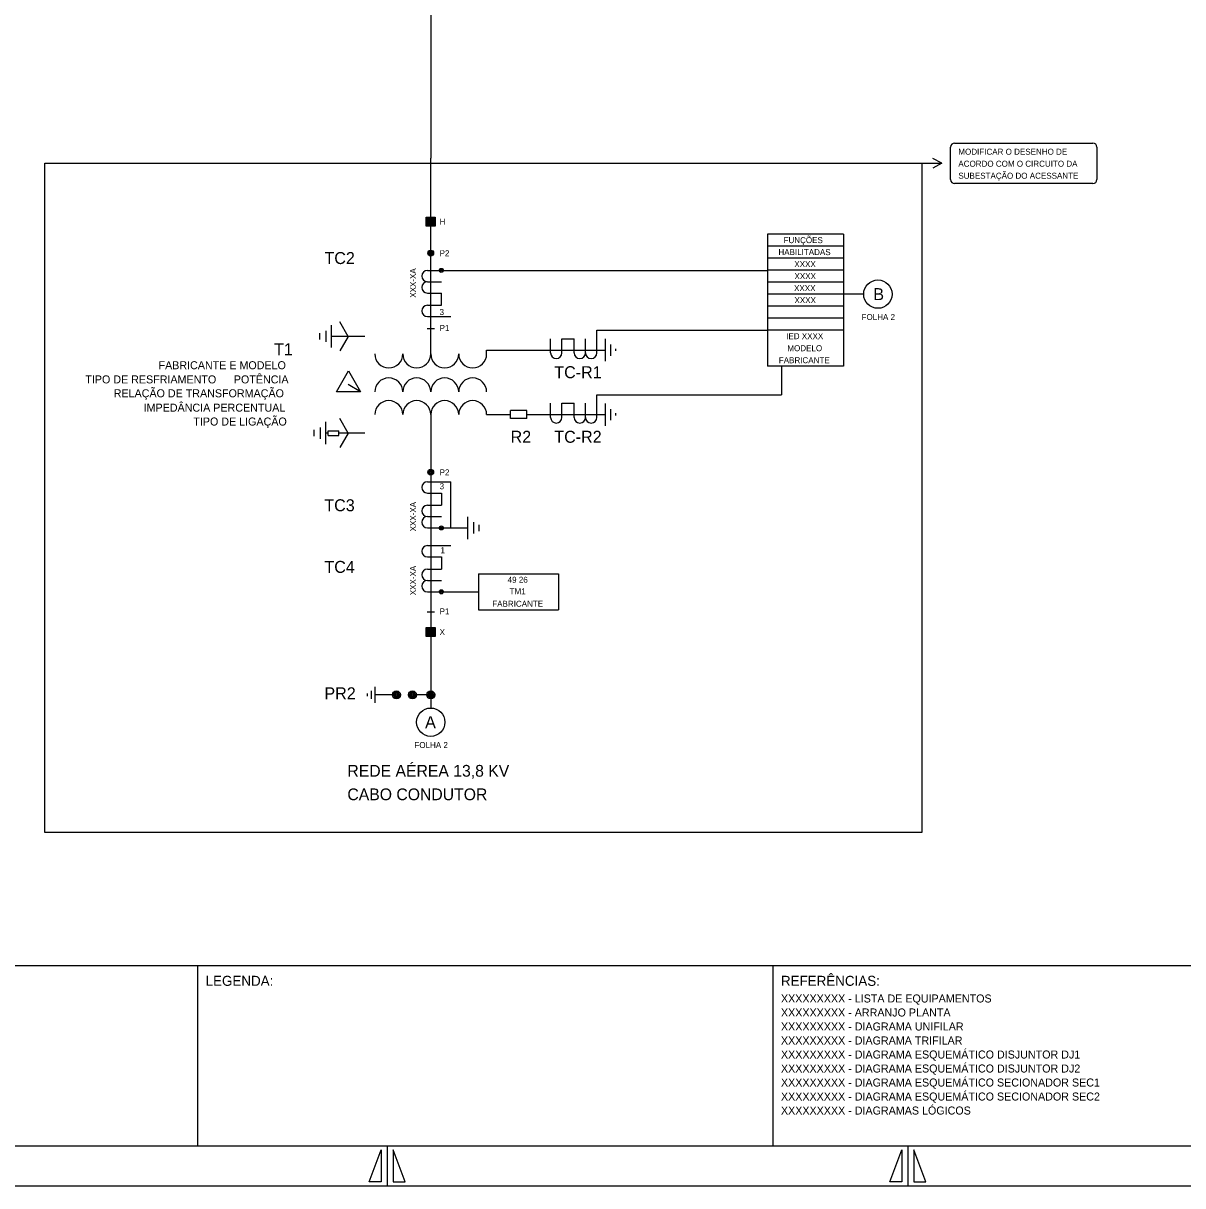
# Model space of a CAD drawing. Extents: x 563 to 1404, y 358 to 952.
# Drawn here: x 812.7 to 1102.2, y 358 to 648.4 of the extents above; entities that cross this region are included whole.
import ezdxf

# ---------------------------------------------------------------- set-up
doc = ezdxf.new("R2010")
doc.units = 0
doc.layers.add('New Level (0)', color=7, linetype='Continuous')

msp = doc.modelspace()

# ---------------------------------------------------------------- linework, layer by layer
for p, q in [((914.46, 705.43), (914.46, 614.76)), ((914.46, 565.81), (914.46, 614.76)), ((913.34, 597.79), (915.49, 599.94)), ((913.34, 597.96), (915.32, 599.94)), ((913.34, 598.14), (915.14, 599.94)), ((913.34, 598.32), (914.96, 599.94)), ((913.34, 598.49), (914.79, 599.94)), ((913.34, 598.67), (914.61, 599.94)), ((913.34, 598.85), (914.43, 599.94)), ((913.34, 599.02), (914.26, 599.94)), ((913.34, 599.2), (914.08, 599.94)), ((913.34, 599.38), (913.9, 599.94)), ((913.34, 599.55), (913.73, 599.94)), ((913.34, 599.73), (913.55, 599.94)), ((913.34, 599.91), (913.37, 599.94)), ((913.46, 597.73), (915.55, 599.82)), ((913.64, 597.73), (915.55, 599.64)), ((913.81, 597.73), (915.55, 599.47)), ((913.99, 597.73), (915.55, 599.29)), ((914.17, 597.73), (915.55, 599.11)), ((914.34, 597.73), (915.55, 598.94)), ((914.52, 597.73), (915.55, 598.76)), ((914.7, 597.73), (915.55, 598.58)), ((914.87, 597.73), (915.55, 598.41)), ((915.05, 597.73), (915.55, 598.23)), ((915.23, 597.73), (915.55, 598.05)), ((915.4, 597.73), (915.55, 597.88)), ((998.51, 595.74), (998.51, 562.74)), ((1017.49, 595.74), (998.51, 595.74)), ((1017.49, 595.74), (1017.49, 562.74)), ((1017.49, 592.74), (998.51, 592.74)), ((1017.49, 589.74), (998.51, 589.74)), ((913.64, 586.67), (998.51, 586.67)), ((1017.49, 586.74), (998.51, 586.74)), ((913.64, 583.84), (917.18, 583.84)), ((913.64, 581.01), (917.18, 581.01)), ((917.18, 577.96), (917.18, 581.01)), ((1017.49, 583.74), (998.51, 583.74)), ((1022.57, 580.74), (998.51, 580.74)), ((913.64, 577.96), (917.18, 577.96)), ((1017.49, 577.74), (998.51, 577.74)), ((1017.49, 577.74), (998.51, 577.74)), ((889.65, 567.4), (889.65, 572.99)), ((893.84, 570.19), (891.75, 573.82)), ((913.64, 575.13), (919.51, 575.13)), ((1017.49, 574.74), (998.51, 574.74)), ((886.77, 569.41), (886.77, 570.97)), ((888.25, 571.59), (888.25, 568.8)), ((898.03, 570.19), (889.65, 570.19)), ((893.84, 570.19), (891.75, 566.56)), ((944.39, 566.07), (944.39, 569.61)), ((947.22, 569.61), (950.27, 569.61)), ((947.22, 566.07), (947.22, 569.61)), ((950.27, 566.07), (950.27, 569.61)), ((953.1, 566.07), (953.1, 569.61)), ((955.93, 566.07), (955.93, 571.74)), ((955.93, 571.74), (998.51, 571.74)), ((958.05, 569.56), (958.05, 563.98)), ((1017.49, 571.74), (998.51, 571.74)), ((928.42, 566.77), (958.05, 566.77)), ((928.42, 565.81), (928.42, 566.77)), ((959.44, 565.37), (959.44, 568.17)), ((960.61, 567.11), (960.61, 566.57)), ((890.88, 556.32), (893.91, 561.56)), ((893.91, 561.56), (896.93, 556.32)), ((1017.49, 562.74), (998.51, 562.74)), ((1002.01, 562.74), (1002.01, 555.6)), ((896.93, 556.32), (893.84, 558.19)), ((896.93, 556.32), (890.88, 556.32)), ((955.93, 549.94), (955.93, 555.6)), ((955.93, 555.6), (1002.01, 555.6)), ((944.39, 549.94), (944.39, 553.48)), ((947.22, 553.48), (950.27, 553.48)), ((947.22, 549.94), (947.22, 553.48)), ((950.27, 549.94), (950.27, 553.48)), ((953.1, 549.94), (953.1, 553.48)), ((958.05, 553.43), (958.05, 547.84)), ((959.44, 549.24), (959.44, 552.03)), ((893.84, 546.02), (891.75, 549.65)), ((928.42, 550.64), (934.39, 550.64)), ((934.39, 549.63), (934.39, 551.65)), ((938.42, 551.65), (934.39, 551.65)), ((938.42, 549.63), (934.39, 549.63)), ((938.42, 549.63), (938.42, 551.65)), ((938.42, 550.64), (958.05, 550.64)), ((960.61, 550.98), (960.61, 550.44)), ((885.38, 545.24), (885.38, 546.8)), ((886.86, 547.42), (886.86, 544.62)), ((888.25, 543.23), (888.25, 548.81)), ((888.83, 546.02), (888.25, 546.02)), ((898.03, 546.02), (891.52, 546.02)), ((893.84, 546.02), (891.75, 542.39)), ((913.64, 533.87), (919.51, 533.87)), ((913.64, 531.04), (917.18, 531.04)), ((917.18, 531.04), (917.18, 527.99)), ((913.64, 527.99), (917.18, 527.99)), ((913.64, 525.16), (917.18, 525.16)), ((923.7, 519.54), (923.7, 525.12)), ((925.1, 523.73), (925.1, 520.93)), ((926.58, 521.55), (926.58, 523.11)), ((913.64, 522.33), (917.18, 522.33)), ((917.18, 522.33), (923.7, 522.33)), ((913.64, 517.91), (919.51, 517.91)), ((913.64, 515.08), (917.18, 515.08)), ((917.18, 515.08), (917.18, 512.03)), ((913.64, 512.03), (917.18, 512.03)), ((913.64, 509.2), (917.18, 509.2)), ((926.38, 510.87), (926.38, 501.87)), ((926.38, 510.87), (946.37, 510.87)), ((946.37, 510.87), (946.37, 501.87)), ((913.64, 506.37), (926.38, 506.37)), ((913.64, 506.37), (917.18, 506.37)), ((926.38, 501.87), (946.37, 501.87)), ((913.34, 495.27), (915.49, 497.42)), ((913.34, 495.44), (915.32, 497.42)), ((913.34, 495.62), (915.14, 497.42)), ((913.34, 495.8), (914.96, 497.42)), ((913.34, 495.97), (914.79, 497.42)), ((913.34, 496.15), (914.61, 497.42)), ((913.34, 496.33), (914.43, 497.42)), ((913.34, 496.5), (914.26, 497.42)), ((913.34, 496.68), (914.08, 497.42)), ((913.34, 496.86), (913.9, 497.42)), ((913.34, 497.04), (913.73, 497.42)), ((913.34, 497.21), (913.55, 497.42)), ((913.34, 497.39), (913.37, 497.42)), ((913.46, 495.21), (915.55, 497.3)), ((913.64, 495.21), (915.55, 497.12)), ((913.81, 495.21), (915.55, 496.95)), ((913.99, 495.21), (915.55, 496.77)), ((914.17, 495.21), (915.55, 496.59)), ((914.34, 495.21), (915.55, 496.42)), ((914.52, 495.21), (915.55, 496.24)), ((914.7, 495.21), (915.55, 496.06)), ((914.87, 495.21), (915.55, 495.89)), ((915.05, 495.21), (915.55, 495.71)), ((915.23, 495.21), (915.55, 495.53)), ((915.4, 495.21), (915.55, 495.36)), ((900.57, 478.62), (900.57, 482.62)), ((898.57, 480.92), (898.57, 480.32)), ((898.57, 480.62), (898.57, 480.62)), ((899.57, 481.62), (899.57, 479.62)), ((901.89, 480.62), (900.57, 480.62)), ((905.89, 480.62), (901.89, 480.62)), ((914.47, 480.62), (909.89, 480.62))]:
    msp.add_line(p, q)
for points in [[(913.34, 599.94), (915.55, 599.94), (915.55, 597.73), (913.34, 597.73)], [(913.34, 497.42), (915.55, 497.42), (915.55, 495.21), (913.34, 495.21)]]:
    msp.add_lwpolyline(points, close=True)
for centre, radius in [((914.45, 591.01), 0.729), ((914.46, 591), 0.511), ((914.46, 591), 0.288), ((917.09, 586.67), 0.511), ((917.09, 586.67), 0.288), ((914.45, 536.24), 0.729), ((914.46, 536.24), 0.511), ((914.46, 536.24), 0.288), ((917.1, 522.33), 0.511), ((917.1, 522.33), 0.288), ((917.09, 506.37), 0.511), ((917.09, 506.37), 0.288), ((905.89, 480.62), 1), ((905.89, 480.62), 0.75), ((905.89, 480.62), 0.5), ((905.89, 480.62), 0.25), ((909.89, 480.62), 1), ((909.89, 480.62), 0.75), ((909.89, 480.62), 0.5), ((909.89, 480.62), 0.25), ((914.47, 480.62), 1), ((914.47, 480.62), 0.75), ((914.47, 480.62), 0.5), ((914.47, 480.62), 0.25)]:
    msp.add_circle(centre, radius)
for centre, radius, start, end in [((913.64, 585.26), 1.42, 90, 270), ((913.64, 582.43), 1.42, 90, 270), ((913.64, 576.54), 1.42, 90, 270), ((903.98, 565.81), 3.49, 180, 0), ((910.96, 565.81), 3.49, 180, 0), ((917.95, 565.81), 3.49, 180, 0), ((924.93, 565.81), 3.49, 180, 0), ((945.8, 566.07), 1.42, 180, 0), ((951.68, 566.07), 1.42, 180, 0), ((954.51, 566.07), 1.42, 180, 0), ((903.98, 556.32), 3.49, 0, 180), ((910.96, 556.32), 3.49, 0, 180), ((917.95, 556.32), 3.49, 0, 180), ((924.93, 556.32), 3.49, 0, 180), ((903.98, 550.64), 3.49, 0, 180), ((910.96, 550.64), 3.49, 0, 180), ((917.95, 550.64), 3.49, 0, 180), ((924.93, 550.64), 3.49, 0, 180), ((945.8, 549.94), 1.42, 180, 0), ((951.68, 549.94), 1.42, 180, 0), ((954.51, 549.94), 1.42, 180, 0), ((913.64, 532.46), 1.42, 90, 270), ((913.64, 526.58), 1.42, 90, 270), ((913.64, 523.75), 1.42, 90, 270), ((913.64, 516.5), 1.42, 90, 270), ((913.64, 510.62), 1.42, 90, 270), ((913.64, 507.79), 1.42, 90, 270)]:
    msp.add_arc(centre, radius, start, end)
at = {"layer": 'New Level (0)'}
for p, q in [((1044.27, 609.37), (1044.27, 617.49)), ((1045.27, 618.49), (1052.62, 618.49)), ((1052.62, 618.49), (1079.81, 618.49)), ((1080.81, 617.49), (1080.81, 609.37)), ((1037.08, 613.43), (1042.11, 613.43)), ((1042.11, 613.43), (1039.81, 614.64)), ((1042.11, 613.43), (1039.81, 612.22)), ((1079.81, 608.37), (1045.27, 608.37)), ((913.56, 572.17), (915.36, 572.17)), ((914.46, 550.64), (914.46, 477.34)), ((888.83, 546.02), (888.83, 546.63)), ((888.83, 546.63), (891.52, 546.63)), ((891.52, 545.41), (891.52, 546.63)), ((888.83, 545.41), (888.83, 546.02)), ((888.83, 545.41), (891.52, 545.41)), ((919.51, 522.33), (919.51, 533.87)), ((913.56, 501.35), (915.36, 501.35)), ((572.58, 412.96), (1393.58, 412.96)), ((856.24, 412.96), (856.24, 367.96)), ((999.91, 412.96), (999.91, 367.96)), ((572.58, 367.96), (1393.58, 367.96)), ((572.58, 367.96), (1393.58, 367.96)), ((899.08, 358.96), (902.08, 366.96)), ((902.08, 366.96), (902.08, 358.96)), ((903.58, 367.96), (903.58, 357.96)), ((905.08, 366.96), (905.08, 358.96)), ((908.08, 358.96), (905.08, 366.96)), ((1029.08, 358.96), (1032.08, 366.96)), ((1032.08, 366.96), (1032.08, 358.96)), ((1033.58, 367.96), (1033.58, 357.96)), ((1035.08, 366.96), (1035.08, 358.96)), ((1038.08, 358.96), (1035.08, 366.96)), ((562.58, 357.96), (1403.58, 357.96)), ((562.58, 357.96), (1403.58, 357.96)), ((902.08, 358.96), (899.08, 358.96)), ((905.08, 358.96), (908.08, 358.96)), ((1032.08, 358.96), (1029.08, 358.96)), ((1035.08, 358.96), (1038.08, 358.96))]:
    msp.add_line(p, q, dxfattribs=at)
msp.add_lwpolyline([(818.09, 613.43), (1037.08, 613.43), (1037.08, 446.19), (818.09, 446.19)], close=True, dxfattribs=at)
for centre in [(1026.11, 580.74), (914.46, 473.79)]:
    msp.add_circle(centre, 3.54, dxfattribs=at)
for centre, start, end in [((1045.27, 617.49), 90, 180), ((1079.81, 617.49), 0, 90), ((1045.27, 609.37), 180, 270), ((1079.81, 609.37), 270, 0)]:
    msp.add_arc(centre, 1, start, end, dxfattribs=at)

# ---------------------------------------------------------------- texts
for s, height, p in [('MODIFICAR O DESENHO DE ', 1.5, (1046.21, 615.58)), ('ACORDO COM O CIRCUITO DA ', 1.5, (1046.21, 612.58)), ('SUBESTAÇÃO DO ACESSANTE', 1.5, (1046.21, 609.58)), ('H', 1.5, (916.67, 598.09)), ('FUNÇÕES ', 1.5, (1002.57, 593.49)), ('TC2', 3, (887.92, 588.26)), ('P2', 1.5, (916.67, 590.23)), ('HABILITADAS', 1.5, (1001.28, 590.49)), ('XXXX', 1.5, (1005.26, 587.49)), ('XXXX', 1.5, (1005.29, 584.49)), ('XXXX', 1.5, (1005.19, 581.49)), ('B', 3, (1024.98, 579.24)), ('XXXX', 1.5, (1005.29, 578.49)), ('3', 1.5, (916.66, 575.53)), ('FOLHA 2', 1.5, (1022.04, 574.28)), ('P1', 1.5, (916.67, 571.55)), ('IED XXXX', 1.5, (1003.22, 569.49)), ('T1', 3, (875.33, 565.45)), ('MODELO', 1.5, (1003.51, 566.49)), ('FABRICANTE E MODELO', 2, (846.48, 561.98)), ('FABRICANTE', 1.5, (1001.38, 563.49)), ('POTÊNCIA', 2, (865.28, 558.44)), ('TC-R1', 3, (945.32, 559.74)), ('TIPO DE RESFRIAMENTO ', 2, (828.2, 558.44)), ('RELAÇÃO DE TRANSFORMAÇÃO', 2, (835.29, 554.97)), ('IMPEDÂNCIA PERCENTUAL', 2, (842.76, 551.38)), ('TIPO DE LIGAÇÃO', 2, (855.17, 547.91)), ('R2', 3, (934.4, 543.6)), ('TC-R2', 3, (945.32, 543.6)), ('P2', 1.5, (916.67, 535.46)), ('3', 1.5, (916.67, 531.99)), ('TC3', 3, (887.89, 526.49)), ('1', 1.5, (916.88, 516.02)), ('TC4', 3, (887.91, 511.09)), ('49 26', 1.5, (933.66, 508.62)), ('TM1', 1.5, (934.14, 505.73)), ('FABRICANTE', 1.5, (929.82, 502.62)), ('P1', 1.5, (916.67, 500.72)), ('X', 1.5, (916.67, 495.57)), ('PR2', 3, (887.91, 479.5)), ('A', 3, (913.05, 472.29)), ('FOLHA 2', 1.5, (910.38, 467.33)), ('REDE AÉREA 13,8 KV', 2.94, (893.64, 460.17)), ('CABO CONDUTOR ', 2.94, (893.64, 454.29))]:
    msp.add_text(s, height=height).set_placement(p)
for p in [(910.77, 579.85), (910.77, 521.47), (910.77, 505.51)]:
    msp.add_text('XXX-XA', height=1.5, rotation=90).set_placement(p)
for s, height, p in [('LEGENDA:', 2.5, (858.24, 407.91)), ('REFERÊNCIAS:', 2.5, (1001.91, 407.91)), ('XXXXXXXXX - LISTA DE EQUIPAMENTOS', 2, (1001.91, 403.75)), ('XXXXXXXXX - ARRANJO PLANTA', 2, (1001.91, 400.25)), ('XXXXXXXXX - DIAGRAMA UNIFILAR', 2, (1001.91, 396.75)), ('XXXXXXXXX - DIAGRAMA TRIFILAR', 2, (1001.91, 393.25)), ('XXXXXXXXX - DIAGRAMA ESQUEMÁTICO DISJUNTOR DJ1', 2, (1001.91, 389.75)), ('XXXXXXXXX - DIAGRAMA ESQUEMÁTICO DISJUNTOR DJ2', 2, (1001.91, 386.25)), ('XXXXXXXXX - DIAGRAMA ESQUEMÁTICO SECIONADOR SEC1', 2, (1001.91, 382.75)), ('XXXXXXXXX - DIAGRAMA ESQUEMÁTICO SECIONADOR SEC2', 2, (1001.91, 379.25)), ('XXXXXXXXX - DIAGRAMAS LÓGICOS', 2, (1001.91, 375.75))]:
    msp.add_text(s, height=height, dxfattribs=at).set_placement(p)

doc.saveas('drawing.dxf')
